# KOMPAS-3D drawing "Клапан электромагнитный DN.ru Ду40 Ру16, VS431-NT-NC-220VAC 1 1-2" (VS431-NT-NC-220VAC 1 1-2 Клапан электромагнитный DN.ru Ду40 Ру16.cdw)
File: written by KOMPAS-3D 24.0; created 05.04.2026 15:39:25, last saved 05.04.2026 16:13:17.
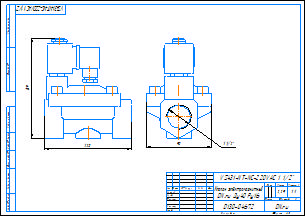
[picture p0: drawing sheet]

Document properties: c3d_UniqueCompID: ef56311e-7521-43dc-8291-0e6108b3d81d; Автор: artio; Класс точности: c; Знак неуказанной шероховатости: Шероховатость не задана; Рассекать на разрезах: Да; c3d_UniqueCompID: ef56311e-7521-43dc-8291-0e6108b3d81d; Автор: artio; Класс точности: c; Знак неуказанной шероховатости: Шероховатость не задана; Рассекать на разрезах: Да; c3d_UniqueCompID: ef56311e-7521-43dc-8291-0e6108b3d81d; Автор: artio; Класс точности: c; Знак неуказанной шероховатости: Шероховатость не задана; Рассекать на разрезах: Да; c3d_UniqueCompID: ef56311e-7521-43dc-8291-0e6108b3d81d; Автор: artio; Класс точности: c; Знак неуказанной шероховатости: Шероховатость не задана; Рассекать на разрезах: Да; Автор: artio; Форматы листов документа: A3; Полное имя файла: VS431-NT-NC-220VAC 1 1-2 Клапан электромагнитный DN.ru Ду40 Ру16.m3d; Масса: 2.285; Наименование: Клапан электромагнитный DN.ru Ду40 Ру16; Количество листов документа: 1; Примечание: D130-04672

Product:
- Body: Тело 1  | qty 1
    Масса: 3.859459
- Part/product: Клапан электромагнитный DN.ru Ду40 Ру16  | designation VS431-NT-NC-220VAC 1 1-2
    Масса: 2.285
    Раздел спецификации: Прочие изделия
    Примечание: D130-04672
    additional columns: ef56311e-7521-43dc-8291-0e6108b3d81d; artio; c; Шероховатость не задана; Да

Views: Вид 1, Спереди
Referenced files in C:\Users\artio\OneDrive\Рабочий стол\Клапан электромагнитный DN.ru\VS431\VS431-ET-NC\: VS431-ET-NC-220VAC 3-4 Клапан электромагнитный DN.ru Ду20 Ру16.m3d, VS431-ET-NC-220VAC 3-4 Клапан электромагнитный DN.ru Ду20 Ру16.cdw
Referenced files in C:\Users\artio\OneDrive\Рабочий стол\Клапан электромагнитный DN.ru\VS431\VS431-NT-NC\: VS431-NT-NC-220VAC 1 1-2 Клапан электромагнитный DN.ru Ду40 Ру16.m3d
Referenced files in C:\Users\artio\OneDrive\Рабочий стол\Клапан электромагнитный DN.ru\VS431\VS431-NT-NC\VS431-NT-NC-220VAC\Ду40\: VS431-NT-NC-220VAC 1 1-2 Клапан электромагнитный DN.ru Ду40 Ру16.m3d
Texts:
  VS431-NT-NC-220VAC 1 1-2
  Клапан электромагнитный
  DN.ru Ду40 Ру16
  VS431-NT-NC-220VAC 1 1/2"
  VS431-NT-NC-220VAC 1 1/2"-
  Клапан электромагнитный DN.ru Ду40 Ру16
  VS431-NT-NC-220VAC 1 1-2 Клапан электромагнитный DN.ru Ду40 Ру16
Dimensions and other numbers on the sheet: 0; 3; 2; 4; 90; 1 1/2"; 1:1; 1; 2,29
